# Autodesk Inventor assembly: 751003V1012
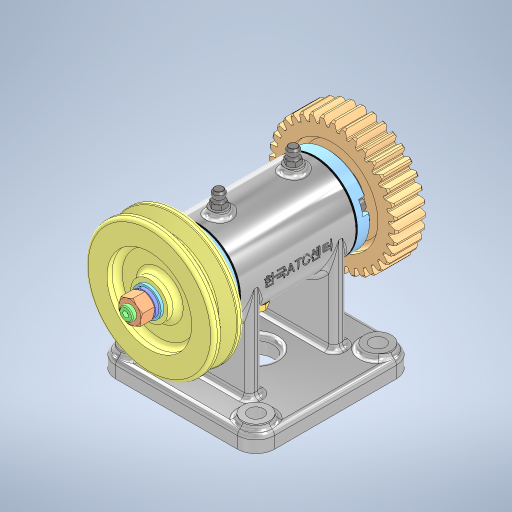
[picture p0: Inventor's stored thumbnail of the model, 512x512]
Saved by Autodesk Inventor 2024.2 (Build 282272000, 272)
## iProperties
Created: 2025-10
Part Number: 751003V1012
Document SubType Name: Assembly
Designer: home
Author: home
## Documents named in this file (17)
- C:\Users\home\Desktop\751003V1012\751003V1012.iam
- C:\Users\home\Desktop\751003V1012\751003V1012.ipt
- C:\Users\home\Desktop\750903V1008\평 와셔 M8\평 와셔 M8.ipt
- C:\Users\home\Desktop\750903V1008\6각 구멍붙이 볼트 M4x10\6각 구멍붙이 볼트 M4x10.ipt
- C:\Users\home\Desktop\750903V1008\6각 너트 M8x1\6각 너트 M8x1.ipt
- C:\Users\home\Desktop\750903V1008\6각 머리 볼트 M6x0.75x8\6각 머리 볼트 M6x0.75x8.ipt
- C:\Users\home\Desktop\750903V1008\V 벨트 풀리\V 벨트 풀리.ipt
- C:\Users\home\Desktop\750903V1008\가스켓\가스켓.ipt
- C:\Users\home\Desktop\750903V1008\그리스 니플 M6x0.75\그리스 니플 M6x0.75.ipt
- C:\Users\home\Desktop\750903V1008\깊은 홈 볼 베어링 6002\깊은 홈 볼 베어링 6002.ipt
- C:\Users\home\Desktop\750903V1008\스퍼 기어\스퍼 기어.ipt
- C:\Users\home\Desktop\750903V1008\스프링 와셔 M8\스프링 와셔 M8.ipt
- C:\Users\home\Desktop\750903V1008\실링\실링.ipt
- C:\Users\home\Desktop\750903V1008\오일 실 15 25 4\오일 실 15 25 4.ipt
- C:\Users\home\Desktop\750903V1008\축\축.ipt
- C:\Users\home\Desktop\750903V1008\커버\커버.ipt
- C:\Users\home\Desktop\750903V1008\평행 키 3x3x12\평행 키 3x3x12.ipt
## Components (15 placed, 7 different names)
1. 751003V1012:1
2. 6각 구멍붙이 볼트 M4x10:1
3. 6각 너트 M8x1:1
4. 6각 머리 볼트 M6x0.75x8:1
5. V 벨트 풀리:1
6. 가스켓:1
7. 그리스 니플 M6x0.75:1
8. 6각 너트 M8x1:2
9. 가스켓:2
10. 그리스 니플 M6x0.75:2
11. 6각 구멍붙이 볼트 M4x10:2
12. 6각 구멍붙이 볼트 M4x10:3
13. 6각 구멍붙이 볼트 M4x10:4
14. 6각 구멍붙이 볼트 M4x10:5
15. 6각 구멍붙이 볼트 M4x10:6
## Named parameters: d14_d12 = 0, d15_d13 = 0, d23_d17 = 0
